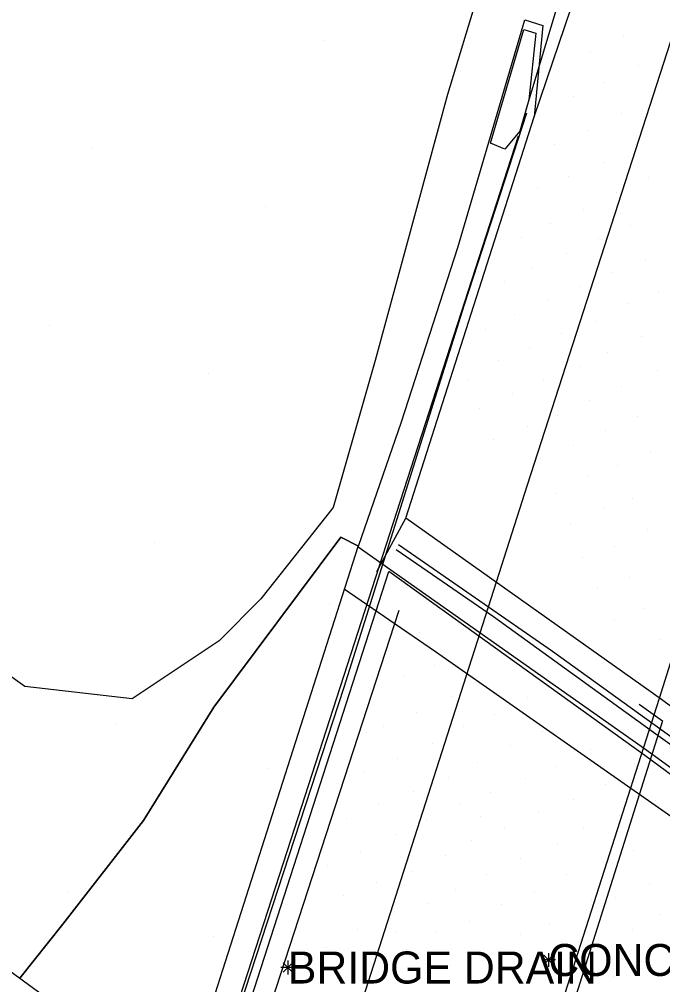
# Model space of a CAD drawing. Extents: x 0 to 1739264, y 0 to 465304.
# Drawn here: x 1738835.1 to 1738871.3, y 464726.9 to 464781.2 of the extents above; entities that cross this region are included whole.
import ezdxf

# ---------------------------------------------------------------- set-up
doc = ezdxf.new("R2010")
doc.units = 0
for name, color, linetype in [('Default', 7, 'Continuous'), ('S_Ground_SpotElevation', 7, 'Continuous'), ('S_Misc_MiscItems', 7, 'Continuous'), ('S_Terrain_Flow_Arrows', 7, 'Continuous'), ('S_Terrain_Holes', 7, 'Continuous'), ('S_Terrain_Imported_Contours', 7, 'Continuous'), ('S_Terrain_Low_Points', 7, 'Continuous'), ('S_Terrain_Major_Contours', 7, 'Continuous'), ('S_Terrain_Major_Contours_Label', 7, 'Continuous'), ('S_Terrain_Minor_Contours', 7, 'Continuous'), ('S_Terrain_Minor_Contours_Label', 7, 'Continuous'), ('S_Terrain_Spots', 7, 'Continuous'), ('S_Terrain_Triangles', 7, 'Continuous'), ('S_Terrain_Voids', 7, 'Continuous'), ('S_Terrain_XSC', 7, 'Continuous'), ('S_Text', 7, 'Continuous')]:
    doc.layers.add(name, color=color, linetype=linetype)

# ---------------------------------------------------------------- blocks, each defined once
blk = doc.blocks.new('POINT_DISPLAY')
at = {"layer": 'Default'}
blk.add_line((0, 0), (0, 0), dxfattribs=at)

msp = doc.modelspace()

# ---------------------------------------------------------------- linework, layer by layer
at = {"layer": 'S_Misc_MiscItems'}
for p, q in [((1738864.856, 464728.697325), (1738864.856, 464727.911475)), ((1738850.467081, 464727.618219), (1738849.942919, 464728.142381)), ((1738850.467081, 464728.142381), (1738849.942919, 464727.618219)), ((1738850.205, 464728.273225), (1738850.205, 464727.487375)), ((1738865.248925, 464728.3044), (1738864.463075, 464728.3044)), ((1738865.118081, 464728.042319), (1738864.593919, 464728.566481)), ((1738865.118081, 464728.566481), (1738864.593919, 464728.042319)), ((1738850.597925, 464727.8803), (1738849.812075, 464727.8803))]:
    msp.add_line(p, q, dxfattribs=at)
at = {"layer": 'S_Terrain_Flow_Arrows'}
msp.add_lwpolyline([(1738863.630953, 464776.21538), (1738870.686392, 464799.630539), (1738880.976542, 464833.335904), (1738891.521163, 464866.875576), (1738902.043999, 464898.625628), (1738909.449429, 464920.708369), (1738913.978443, 464935.285724), (1738920.614184, 464955.386879), (1738925.674578, 464970.046684), (1738928.490262, 464978.707), (1738928.944482, 464980.321555), (1738929.1364, 464982.423626), (1738929.316001, 464984.590963), (1738928.958563, 464986.728954), (1738928.523169, 464988.225434), (1738927.631668, 464989.835786), (1738926.762617, 464991.075628), (1738925.449805, 464992.429268), (1738923.890981, 464993.932546), (1738921.433107, 464995.760418), (1738918.9424, 464997.220501), (1738915.349001, 464998.823773), (1738908.641695, 465001.556378), (1738904.365908, 465003.320294)], dxfattribs=at)
at = {"layer": 'S_Terrain_Holes'}
for points in [[(1738856.840841, 464753.154236), (1738864.057181, 464775.7454), (1738868.5654, 464789.017493), (1738877.2832, 464816.667503), (1738894.6762, 464871.298499), (1738908.615099, 464914.227276), (1738925.968706, 464967.700787), (1738931.720797, 464985.987408), (1738937.417894, 465002.810894), (1738942.679705, 465019.271282), (1738946.949205, 465031.543377), (1738957.801699, 465065.627422), (1738970.933794, 465105.251873), (1738981.084093, 465138.214092), (1738987.350398, 465160.501376), (1738994.117907, 465180.316815), (1739002.701601, 465206.97459), (1739010.434099, 465230.699413), (1739016.388903, 465250.214703), (1739024.141405, 465271.975903), (1739031.418001, 465292.412487)], [(1738492.982015, 464976.242099), (1738514.851095, 464960.0815), (1738563.791494, 464924.7685), (1738624.996999, 464880.339801), (1738673.015905, 464845.222999), (1738705.323293, 464821.628898), (1738726.980504, 464805.7443), (1738753.122999, 464787.077293), (1738791.7562, 464758.973594), (1738812.206201, 464744.064307), (1738838.2751, 464724.973701), (1738870.6467, 464701.313407), (1738896.6608, 464682.840995), (1738936.578298, 464654.121894), (1738968.041097, 464631.189491), (1739001.793905, 464606.514411), (1739033.507696, 464583.63401), (1739053.896306, 464568.752204), (1739082.668798, 464547.766914), (1739122.612798, 464519.166297), (1739150.551503, 464498.742286), (1739185.599386, 464473.337501), (1739245.296285, 464429.765205)]]:
    msp.add_lwpolyline(points, dxfattribs=at)
at = {"layer": 'S_Terrain_Imported_Contours'}
msp.add_line((1738869.9648, 464742.691331), (1738871.2811, 464741.761298), dxfattribs=at)
for points in [[(1739036.578798, 465290.667492), (1739026.541399, 465259.332012), (1739013.6942, 465219.063488), (1738999.442797, 465174.850323), (1738985.582293, 465132.024273), (1738970.199999, 465085.108929), (1738952.192003, 465029.358624), (1738937.750505, 464984.645672), (1738924.644899, 464943.318829), (1738905.560399, 464884.157001), (1738885.695701, 464823.240203), (1738863.6675, 464755.019294), (1738861.917132, 464749.554455)], [(1738871.099421, 464743.042961), (1738872.2397, 464746.6146), (1738884.148, 464784.717796), (1738894.996801, 464817.751098), (1738911.848199, 464869.926002), (1738930.302797, 464927.737591), (1738944.359194, 464971.624127), (1738958.087007, 465014.085796), (1738974.263903, 465064.602886), (1738992.370806, 465120.419476), (1739017.617296, 465198.443401), (1739037.679499, 465259.797009), (1739046.847902, 465287.700512)], [(1738861.917132, 464749.554455), (1738852.728099, 464720.865302), (1738834.137899, 464663.640296), (1738810.806299, 464591.494392), (1738798.57878, 464553.775144)], [(1738807.560265, 464547.101191), (1738818.883699, 464581.650611), (1738840.7733, 464649.227912), (1738859.7717, 464707.561698), (1738871.099421, 464743.042961)], [(1738871.2811, 464741.761298), (1738862.9528, 464715.336097), (1738835.861902, 464631.717414), (1738814.1443, 464564.731208), (1738808.177672, 464546.642409)]]:
    msp.add_lwpolyline(points, dxfattribs=at)
at = {"layer": 'S_Terrain_Low_Points'}
for points in [[(1738835.128465, 464727.278024), (1738837.556501, 464730.310996), (1738842.0813, 464736.149802), (1738846.0372, 464742.531699), (1738853.1848, 464752.099906), (1738854.1777, 464751.584098)], [(1738792.605864, 464561.753915), (1738808.947702, 464611.187598), (1738829.7665, 464675.843208), (1738844.662601, 464721.815192), (1738854.169417, 464751.567291)], [(1738853.3716, 464749.177695), (1738858.5024, 464745.655708), (1738872.1784, 464736.0951), (1738883.3875, 464728.0783)], [(1738856.4555, 464747.969505), (1738838.244399, 464692.009101), (1738826.647699, 464655.847602), (1738824.734399, 464649.915199), (1738812.578801, 464612.657905), (1738795.808896, 464560.843085)]]:
    msp.add_lwpolyline(points, dxfattribs=at)
at = {"layer": 'S_Terrain_Major_Contours'}
msp.add_lwpolyline([(1738863.468951, 464780.651166), (1738864.151027, 464780.454413), (1738863.757522, 464776.702994), (1738863.259082, 464774.93222), (1738862.406487, 464773.922223), (1738861.606359, 464774.263261), (1738863.468951, 464780.651166)], dxfattribs=at)
at = {"layer": 'S_Terrain_Major_Contours_Label'}
msp.add_line((1738856.340829, 464753.508813), (1738863.169, 464774.664405), dxfattribs=at)
msp.add_lwpolyline([(1738793.029831, 464557.898451), (1738803.9838, 464591.509406), (1738812.589898, 464618.183295), (1738822.305799, 464648.240607), (1738833.2133, 464681.803199), (1738842.84, 464711.786903), (1738850.196, 464734.470405), (1738856.340829, 464753.508813)], dxfattribs=at)
at = {"layer": 'S_Terrain_Minor_Contours'}
msp.add_lwpolyline([(1738835.762039, 464687.932576), (1738847.598619, 464724.443536), (1738855.882145, 464750.170609)], dxfattribs=at)
at = {"layer": 'S_Terrain_Minor_Contours_Label'}
msp.add_line((1738855.2192, 464750.170609), (1738856.840841, 464753.154236), dxfattribs=at)
for points in [[(1738884.962612, 464732.772667), (1738871.227336, 464742.952252), (1738856.840841, 464753.154236)], [(1738884.962612, 464732.772667), (1738871.227336, 464742.952252), (1738856.840841, 464753.154236)], [(1738884.516023, 464731.481904), (1738876.0371, 464737.769508), (1738865.0884, 464745.6603), (1738856.423663, 464751.656029)], [(1738884.41171, 464731.223421), (1738876.6018, 464736.9374), (1738870.772589, 464741.112098), (1738861.763167, 464747.609825), (1738856.295528, 464751.38051)], [(1738883.905735, 464729.730556), (1738870.2911, 464739.801795), (1738855.882145, 464750.170609)]]:
    msp.add_lwpolyline(points, dxfattribs=at)
at = {"layer": 'S_Terrain_Spots'}
msp.add_lwpolyline([(1738854.1777, 464751.584098), (1738853.1848, 464752.099906), (1738846.0372, 464742.531699), (1738842.0813, 464736.149802), (1738837.556501, 464730.310996), (1738835.128465, 464727.278024)], dxfattribs=at)
at = {"layer": 'S_Terrain_Triangles'}
for points in [[(1738856.448989, 464753.432112), (1738860.1495, 464765.184501), (1738863.6532, 464775.975806)], [(1738793.143077, 464557.8143), (1738794.925598, 464563.221652), (1738800.413936, 464580.303997), (1738804.057897, 464591.416999), (1738810.426301, 464610.960395), (1738818.2273, 464635.285011), (1738828.789701, 464667.726112), (1738838.3903, 464697.576408), (1738845.034101, 464718.107597), (1738853.3717, 464743.659003), (1738856.448989, 464753.432112)]]:
    msp.add_lwpolyline(points, dxfattribs=at)
at = {"layer": 'S_Terrain_Voids'}
for points in [[(1738862.0848, 464786.589301), (1738859.1925, 464776.997001), (1738855.1137, 464762.028297)], [(1738855.1137, 464762.028297), (1738852.763601, 464753.768806), (1738848.6921, 464748.632499), (1738846.3355, 464746.267097), (1738841.4575, 464742.999397), (1738835.417501, 464743.694907), (1738828.9097, 464748.336906), (1738815.1737, 464760.669501), (1738803.015996, 464772.060706), (1738800.113103, 464778.163596), (1738797.600698, 464782.422996)]]:
    msp.add_lwpolyline(points, dxfattribs=at)
at = {"layer": 'S_Terrain_XSC'}
for points in [[(1738859.7719, 464768.393195), (1738863.541114, 464781.202273), (1738864.553742, 464780.887039), (1738864.057181, 464775.7454)], [(1738854.163956, 464751.555463), (1738854.1777, 464751.584098), (1738856.5933, 464758.589393), (1738859.7719, 464768.393195)], [(1738854.163956, 464751.555463), (1738870.399814, 464740.113374), (1738885.731746, 464728.946791), (1738885.754413, 464729.003456), (1738888.932599, 464739.860603)]]:
    msp.add_lwpolyline(points, dxfattribs=at)

# ---------------------------------------------------------------- block references
at = {"layer": 'S_Ground_SpotElevation'}
for p in [(1738869.089397, 464780.26989), (1738852.275193, 464780.05119), (1738867.219493, 464779.441276), (1738869.916194, 464778.610771), (1738868.031795, 464777.694816), (1738862.522996, 464777.219402), (1738866.253993, 464776.90789), (1738870.727901, 464776.69091), (1738868.978496, 464775.915886), (1738867.091807, 464774.96862), (1738839.184998, 464774.004284), (1738865.218196, 464774.208305), (1738869.738902, 464774.16851), (1738867.961101, 464773.197502), (1738865.965099, 464772.398613), (1738870.494304, 464772.302177), (1738864.259593, 464771.775322), (1738868.681804, 464771.502373), (1738848.960496, 464770.684918), (1738866.817104, 464770.527275), (1738864.9602, 464769.739494), (1738869.457896, 464769.627983), (1738863.319408, 464768.930412), (1738867.688594, 464768.909599), (1738865.857402, 464768.060417), (1738863.988994, 464767.26519), (1738870.300304, 464767.707817), (1738868.415507, 464766.957817), (1738862.368404, 464766.499321), (1738866.619502, 464766.221794), (1738871.066997, 464765.887199), (1738864.825099, 464765.394218), (1738869.380199, 464765.249382), (1738862.960902, 464764.646904), (1738836.808106, 464764.023968), (1738867.555797, 464764.245476), (1738861.333202, 464763.789482), (1738865.574, 464763.559318), (1738870.074, 464763.399406), (1738863.784602, 464762.779594), (1738868.193095, 464762.482719), (1738862.0312, 464762.013908), (1738845.726106, 464761.276898), (1738866.652995, 464761.716179), (1738870.976207, 464761.490715), (1738860.378993, 464760.949089), (1738864.596797, 464760.894707), (1738862.820293, 464760.17498), (1738868.993007, 464760.585014), (1738867.193599, 464759.774589), (1738860.970607, 464759.335319), (1738865.386302, 464758.957207), (1738869.848796, 464758.906792), (1738863.695094, 464758.343315), (1738868.049007, 464758.07769), (1738861.762508, 464757.572868), (1738866.245006, 464757.259514), (1738870.579997, 464756.92791), (1738864.439403, 464756.50219), (1738868.771907, 464756.151787), (1738867.030406, 464755.511589), (1738865.290904, 464754.536491), (1738869.602199, 464754.251274), (1738867.964503, 464753.681023), (1738866.098994, 464752.840507), (1738870.420497, 464752.546806), (1738842.717408, 464751.796673), (1738868.592296, 464751.543693), (1738866.774806, 464750.94799), (1738869.406398, 464749.845878), (1738867.624995, 464749.202568), (1738852.539994, 464748.310589), (1738870.256099, 464748.101066), (1738868.558803, 464747.385002), (1738857.584102, 464746.724968), (1738871.173305, 464746.335197), (1738855.826503, 464746.01342), (1738858.459605, 464744.894524), (1738856.721599, 464744.29229), (1738860.995799, 464743.939567), (1738854.867396, 464743.526787), (1738859.387797, 464743.149895), (1738863.661296, 464743.076469), (1738857.466701, 464742.254875), (1738861.839, 464742.093803), (1738840.570695, 464741.592999), (1738855.585796, 464741.445183), (1738860.094096, 464741.417473), (1738853.911998, 464740.692863), (1738854.6366, 464741.111397), (1738864.499202, 464741.135307), (1738858.349193, 464740.45861), (1738862.755595, 464740.383781), (1738867.2438, 464740.160698), (1738856.394405, 464739.662102), (1738849.110001, 464739.076824), (1738860.891093, 464739.422783), (1738865.307201, 464739.166618), (1738854.5321, 464738.861687), (1738859.2326, 464738.583671), (1738863.554393, 464738.498894), (1738868.089, 464738.167473), (1738857.264903, 464737.761894), (1738861.5769, 464737.715874), (1738855.330806, 464737.044487), (1738859.901897, 464737.027092), (1738866.268306, 464737.335197), (1738870.878001, 464737.286613), (1738853.519603, 464736.266594), (1738861.045999, 464736.360007), (1738864.322093, 464736.684563), (1738868.830104, 464736.408012), (1738857.998302, 464736.137871), (1738862.395702, 464735.776665), (1738856.282802, 464735.343803), (1738866.852702, 464735.709709), (1738850.848, 464734.834998), (1738860.558498, 464735.020012), (1738865.378993, 464734.853874), (1738854.274501, 464734.369194), (1738859.076198, 464734.163689), (1738869.664897, 464734.440178), (1738852.460994, 464733.614494), (1738863.283702, 464734.02642), (1738867.981898, 464733.762199), (1738857.213206, 464733.296806), (1738861.405299, 464733.101372), (1738865.850505, 464733.08947), (1738855.191203, 464732.649711), (1738870.552898, 464732.602898), (1738837.852998, 464732.118206), (1738853.329707, 464731.932182), (1738859.648204, 464732.270988), (1738864.063106, 464732.120293), (1738858.040004, 464731.508476), (1738862.1981, 464731.433891), (1738867.274599, 464731.720099), (1738868.620998, 464731.84008), (1738851.449504, 464731.147819), (1738856.150798, 464730.896904), (1738866.992396, 464731.144768), (1738871.117, 464730.853569), (1738860.408, 464730.454887), (1738864.912593, 464730.31469), (1738854.109904, 464730.02227), (1738856.2591, 464729.924705), (1738858.590495, 464729.917778), (1738869.580394, 464730.017021), (1738846.006898, 464729.601971), (1738863.288493, 464729.710503), (1738852.394008, 464729.015495), (1738856.855693, 464728.892509), (1738861.286494, 464728.721184), (1738867.727504, 464729.187065), (1738850.539104, 464728.261772), (1738865.641093, 464728.590568), (1738870.113902, 464728.246818), (1738854.937999, 464728.030693), (1738859.364894, 464727.981987), (1738863.932796, 464727.795463), (1738853.165797, 464727.278801), (1738857.512294, 464727.163872), (1738868.524196, 464727.365166)]:
    msp.add_blockref('POINT_DISPLAY', p, dxfattribs=at)

# ---------------------------------------------------------------- texts
at = {"layer": 'S_Text'}
for s, p in [('CONC SLOPE', (1738864.856, 464727.4044)), ('BRIDGE DRAIN', (1738850.205, 464726.9803))]:
    msp.add_text(s, height=1.8, dxfattribs=at).set_placement(p)

doc.saveas('drawing.dxf')
